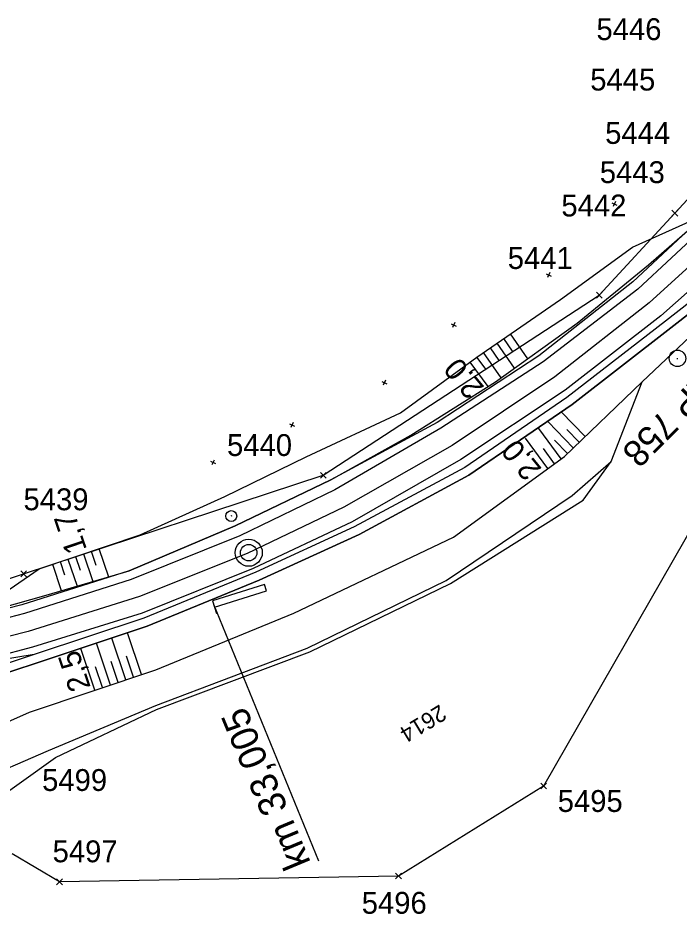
# Model space of a CAD drawing. Extents: x -804166 to -803706, y -1151030 to -1150147.
# Drawn here: x -803967.8 to -803907.3, y -1150746 to -1150663.9 of the extents above; entities that cross this region are included whole.
import ezdxf

# ---------------------------------------------------------------- set-up
doc = ezdxf.new("R2010")
doc.units = 0
for name, color, linetype in [('0381KM032-037P - Vrstva 1', 7, 'Continuous'), ('0381KM032-037P - Vrstva 13', 7, 'Continuous'), ('0381KM032-037P - Vrstva 4', 7, 'Continuous'), ('0381KM032-037P - Vrstva 48', 7, 'Continuous'), ('0381KM032-037P - Vrstva 49', 7, 'Continuous'), ('0381KM032-037P - Vrstva 57', 7, 'Continuous'), ('0381KM032-037P - Vrstva 7', 7, 'Continuous'), ('0381KM032-037P - Vrstva 9', 7, 'Continuous'), ('szdc - hran DP', 7, 'Continuous'), ('szdc - szdc_cislo', 7, 'Continuous'), ('szdc - szdc_krizek', 7, 'Continuous'), ('vyt_sit - stávající', 7, 'Continuous')]:
    doc.layers.add(name, color=color, linetype=linetype)

msp = doc.modelspace()

# ---------------------------------------------------------------- linework, layer by layer
at = {"layer": '0381KM032-037P - Vrstva 1'}
msp.add_lwpolyline([(-803901.906, -1150682.605), (-803910.014, -1150690), (-803918.643, -1150696.775), (-803928.041, -1150703.062), (-803937.946, -1150708.688), (-803946.795, -1150712.932), (-803956.655, -1150716.869), (-803966.853, -1150720.098), (-803973.694, -1150721.813), (-803983.505, -1150723.682), (-803993.918, -1150724.91), (-804004.459, -1150725.421), (-804014.948, -1150725.206), (-804025.475, -1150724.252), (-804035.41, -1150722.673), (-804044.081, -1150720.735), (-804054.774, -1150717.615), (-804061.472, -1150715.138)], dxfattribs=at)
at = {"layer": '0381KM032-037P - Vrstva 13'}
for points in [[(-803902.54, -1150686.99), (-803908.533, -1150691.682), (-803917.537, -1150698.646), (-803926.885, -1150705.063), (-803937.003, -1150710.487), (-803946.017, -1150714.661), (-803956.263, -1150718.85), (-803966.288, -1150722.189), (-803972.538, -1150724.259)], [(-803972.286, -1150725.012), (-803966.125, -1150722.974), (-803955.955, -1150719.581), (-803945.709, -1150715.376), (-803936.565, -1150711.19), (-803926.506, -1150705.78), (-803917.073, -1150699.315), (-803908.044, -1150692.29), (-803902.092, -1150687.65)]]:
    msp.add_lwpolyline(points, dxfattribs=at)
at = {"layer": '0381KM032-037P - Vrstva 4'}
msp.add_line((-803966.288, -1150722.189), (-803973.383, -1150723.337), dxfattribs=at)
for points in [[(-803904.886, -1150683.001), (-803906.516, -1150683.391), (-803911.518, -1150688.069), (-803920.109, -1150694.835), (-803929.412, -1150700.935), (-803939.155, -1150706.209), (-803947.889, -1150710.398), (-803957.601, -1150714.533), (-803967.413, -1150717.637)], [(-803904.886, -1150683.001), (-803911.05, -1150688.735), (-803919.705, -1150695.384), (-803929.087, -1150701.477), (-803938.787, -1150707.105), (-803947.481, -1150711.337), (-803957.418, -1150715.321), (-803967.176, -1150718.433)], [(-803902.503, -1150685.469), (-803908.943, -1150691.185), (-803917.694, -1150697.991), (-803927.241, -1150704.348), (-803937.195, -1150710.055), (-803946.246, -1150714.302), (-803956.405, -1150718.419), (-803966.448, -1150721.526)], [(-803902.503, -1150685.469), (-803902.54, -1150686.99), (-803908.533, -1150691.682), (-803917.537, -1150698.646), (-803926.885, -1150705.063), (-803937.003, -1150710.487), (-803946.017, -1150714.661), (-803956.263, -1150718.85), (-803966.288, -1150722.189)], [(-803967.413, -1150717.637), (-803975.823, -1150719.769), (-803983.88, -1150721.36), (-803994.176, -1150722.403), (-804004.636, -1150722.95), (-804014.864, -1150722.688), (-804025.142, -1150721.989), (-804034.984, -1150720.624), (-804043.408, -1150718.773), (-804051.925, -1150716.215), (-804054.245, -1150715.484), (-804061.999, -1150712.588)], [(-803967.176, -1150718.433), (-803974.218, -1150720.269), (-803983.735, -1150722.132), (-803994.129, -1150723.262), (-804004.519, -1150723.869), (-804015.047, -1150723.539), (-804025.265, -1150722.781), (-804035.168, -1150721.131), (-804043.667, -1150719.322), (-804054.385, -1150716.187), (-804061.833, -1150713.392)], [(-803966.448, -1150721.526), (-803973.383, -1150723.337), (-803975.353, -1150723.792), (-803983.323, -1150725.373), (-803993.816, -1150726.434), (-804004.802, -1150726.955), (-804015.292, -1150726.922), (-804025.602, -1150725.763), (-804035.878, -1150724.109), (-804044.498, -1150722.129), (-804055.401, -1150719.075), (-804061.092, -1150716.98)]]:
    msp.add_lwpolyline(points, dxfattribs=at)
at = {"layer": '0381KM032-037P - Vrstva 48'}
for p, q in [((-803923.341, -1150693.265), (-803922.553, -1150694.407)), ((-803922.724, -1150692.839), (-803921.156, -1150695.111)), ((-803924.575, -1150694.118), (-803923.779, -1150695.271)), ((-803923.958, -1150693.691), (-803922.374, -1150695.987)), ((-803925.193, -1150694.544), (-803923.592, -1150696.863)), ((-803926.415, -1150695.413), (-803924.777, -1150697.655)), ((-803925.809, -1150694.97), (-803924.975, -1150696.112)), ((-803915.883, -1150702.24), (-803918.059, -1150699.974)), ((-803918.079, -1150704.279), (-803920.11, -1150701.499)), ((-803916.965, -1150703.279), (-803919.272, -1150700.876)), ((-803916.424, -1150702.759), (-803917.545, -1150701.592)), ((-803919.291, -1150705.163), (-803921.33, -1150702.372)), ((-803917.506, -1150703.798), (-803918.692, -1150702.563)), ((-803918.685, -1150704.721), (-803919.698, -1150703.334)), ((-803961.787, -1150712.97), (-803960.933, -1150715.502)), ((-803961.077, -1150712.73), (-803960.645, -1150714.011)), ((-803960.366, -1150712.49), (-803959.492, -1150715.083)), ((-803963.919, -1150713.689), (-803963.508, -1150714.91)), ((-803963.209, -1150713.449), (-803962.375, -1150715.921)), ((-803962.498, -1150713.21), (-803962.076, -1150714.461)), ((-803964.63, -1150713.929), (-803963.816, -1150716.341)), ((-803956.479, -1150724.031), (-803957.763, -1150720.201)), ((-803959.324, -1150724.985), (-803960.603, -1150721.167)), ((-803957.902, -1150724.508), (-803959.183, -1150720.684)), ((-803960.746, -1150725.461), (-803962.023, -1150721.65)), ((-803958.613, -1150724.746), (-803959.253, -1150722.836)), ((-803957.19, -1150724.27), (-803957.832, -1150722.356)), ((-803960.035, -1150725.223), (-803960.674, -1150723.316))]:
    msp.add_line(p, q, dxfattribs=at)
at = {"layer": '0381KM032-037P - Vrstva 49'}
for p, q in [((-803913.423, -1150680.841), (-803912.971, -1150681.057)), ((-803913.089, -1150680.723), (-803913.305, -1150681.175)), ((-803919.449, -1150687.332), (-803918.997, -1150687.548)), ((-803919.115, -1150687.214), (-803919.331, -1150687.666)), ((-803928.133, -1150691.918), (-803927.681, -1150692.134)), ((-803927.799, -1150691.8), (-803928.015, -1150692.252)), ((-803934.479, -1150697.185), (-803934.027, -1150697.401)), ((-803934.145, -1150697.067), (-803934.361, -1150697.519)), ((-803942.927, -1150701.07), (-803942.475, -1150701.286)), ((-803942.593, -1150700.952), (-803942.809, -1150701.404)), ((-803950.166, -1150704.501), (-803949.714, -1150704.717)), ((-803949.832, -1150704.383), (-803950.048, -1150704.835))]:
    msp.add_line(p, q, dxfattribs=at)
for points in [[(-803984.817, -1150721.442), (-803974.636, -1150719.233), (-803973.09, -1150718.927), (-803972.805, -1150718.807), (-803972.246, -1150718.741), (-803965.21, -1150716.746), (-803957.601, -1150714.533), (-803947.889, -1150710.398), (-803939.155, -1150706.209), (-803931.831, -1150702.119), (-803924.086, -1150697.218), (-803916.608, -1150691.841), (-803910.081, -1150686.51), (-803906.516, -1150683.391), (-803903.605, -1150681.318)], [(-803972.246, -1150718.741), (-803965.841, -1150714.337), (-803956.596, -1150711.219), (-803948.841, -1150707.727), (-803941.393, -1150704.085), (-803932.776, -1150700.061), (-803925.787, -1150694.954), (-803918.146, -1150689.679), (-803911.549, -1150684.903), (-803903.605, -1150681.318)], [(-803973.24, -1150730.36), (-803966.718, -1150727.463), (-803955.163, -1150723.59), (-803942.536, -1150718.416), (-803927.909, -1150711.458), (-803917.773, -1150704.055), (-803910.649, -1150697.212), (-803903.52, -1150690.487), (-803900.099, -1150686.57)], [(-803902.092, -1150687.65), (-803908.044, -1150692.29), (-803917.073, -1150699.315), (-803926.506, -1150705.78), (-803936.565, -1150711.19), (-803945.709, -1150715.376), (-803955.955, -1150719.581), (-803966.125, -1150722.974), (-803972.286, -1150725.012), (-803974.7, -1150725.768), (-803983.368, -1150727.37), (-803993.836, -1150727.905), (-804004.989, -1150728.615), (-804004.868, -1150729.928), (-804012.985, -1150730.258), (-804018.762, -1150729.808), (-804029.792, -1150728.642), (-804054.152, -1150723.147), (-804060.274, -1150720.943)], [(-803970.39, -1150735.93), (-803964.347, -1150731.606), (-803955.102, -1150727.225), (-803941.078, -1150721.948), (-803928.207, -1150715.68), (-803916.068, -1150708.06), (-803913.504, -1150704.534), (-803910.649, -1150697.212)], [(-803971.76, -1150733.922), (-803964.987, -1150730.973), (-803955.152, -1150726.847), (-803941.304, -1150721.616), (-803928.584, -1150715.413), (-803917.051, -1150707.621), (-803913.504, -1150704.534)]]:
    msp.add_lwpolyline(points, dxfattribs=at)
at = {"layer": '0381KM032-037P - Vrstva 7'}
msp.add_line((-803948.213, -1150709.499), (-803948.305, -1150709.537), dxfattribs=at)
for centre, radius in [((-803948.259, -1150709.518), 0.5), ((-803946.663, -1150712.869), 1.246), ((-803946.663, -1150712.869), 0.752)]:
    msp.add_circle(centre, radius, dxfattribs=at)
at = {"layer": '0381KM032-037P - Vrstva 9'}
for p, q in [((-803945.217, -1150715.777), (-803949.983, -1150717.29)), ((-803945.036, -1150716.348), (-803945.217, -1150715.777)), ((-803949.801, -1150717.862), (-803945.036, -1150716.348)), ((-803949.983, -1150717.29), (-803949.801, -1150717.862)), ((-803949.892, -1150717.576), (-803940.281, -1150741.083)), ((-803949.801, -1150717.862), (-803949.62, -1150718.434))]:
    msp.add_line(p, q, dxfattribs=at)
at = {"layer": 'szdc - hran DP'}
for p, q in [((-803907.67, -1150681.78), (-803903.98, -1150677.77)), ((-803914.58, -1150689.29), (-803907.67, -1150681.78)), ((-803939.84, -1150705.78), (-803914.58, -1150689.29)), ((-803967.26, -1150714.81), (-803939.84, -1150705.78)), ((-803905.7, -1150709.82), (-803919.68, -1150734.23)), ((-803976.9, -1150717.98), (-803967.26, -1150714.81)), ((-803919.68, -1150734.23), (-803932.96, -1150742.47)), ((-803963.98, -1150743), (-803968.3, -1150740.45)), ((-803932.96, -1150742.47), (-803963.98, -1150743))]:
    msp.add_line(p, q, dxfattribs=at)
at = {"layer": 'szdc - szdc_krizek'}
for p, q in [((-803907.405, -1150682.045), (-803907.936, -1150681.515)), ((-803907.936, -1150682.045), (-803907.405, -1150681.515)), ((-803914.315, -1150689.555), (-803914.846, -1150689.025)), ((-803914.846, -1150689.555), (-803914.315, -1150689.025)), ((-803939.575, -1150706.045), (-803940.106, -1150705.515)), ((-803940.106, -1150706.045), (-803939.575, -1150705.515)), ((-803966.995, -1150715.075), (-803967.526, -1150714.545)), ((-803967.526, -1150715.075), (-803966.995, -1150714.545)), ((-803919.415, -1150734.495), (-803919.946, -1150733.965)), ((-803919.946, -1150734.495), (-803919.415, -1150733.965)), ((-803932.695, -1150742.735), (-803933.226, -1150742.205)), ((-803933.226, -1150742.735), (-803932.695, -1150742.205)), ((-803963.715, -1150743.265), (-803964.246, -1150742.735)), ((-803964.246, -1150743.265), (-803963.715, -1150742.735))]:
    msp.add_line(p, q, dxfattribs=at)
at = {"layer": 'vyt_sit - stávající'}
msp.add_line((-803907.48, -1150695.075), (-803907.38, -1150695.075), dxfattribs=at)
msp.add_circle((-803907.43, -1150695.075), 0.756, dxfattribs=at)

# ---------------------------------------------------------------- texts
at = {"layer": '0381KM032-037P - Vrstva 48'}
for s, rotation, p in [('2,0', 129.61944, (-803925.039, -1150697.72)), ('2,0', 129.42518, (-803919.779, -1150705.196)), ('1,7', 108.63737, (-803961.445, -1150712.571)), ('2,5', 108.45016, (-803961.097, -1150725.192))]:
    msp.add_text(s, height=2, rotation=rotation, dxfattribs=at).set_placement(p)
at = {"layer": '0381KM032-037P - Vrstva 57'}
msp.add_text('2614', height=1.5, rotation=211.19956, dxfattribs=at).set_placement((-803929.177, -1150726.725))
at = {"layer": '0381KM032-037P - Vrstva 9'}
msp.add_text('km 33,005', height=2.5, rotation=112.61933, dxfattribs=at).set_placement((-803940.96, -1150741.243))
at = {"layer": 'szdc - szdc_cislo'}
for s, p in [('5446', (-803914.842, -1150665.938)), ('5445', (-803915.41, -1150670.556)), ('5444', (-803914.043, -1150675.44)), ('5443', (-803914.536, -1150679.031)), ('5442', (-803918.052, -1150682.083)), ('5441', (-803922.96, -1150686.892)), ('5440', (-803948.647, -1150704.016)), ('5439', (-803967.272, -1150708.982)), ('5499', (-803965.569, -1150734.683)), ('5495', (-803918.385, -1150736.604)), ('5497', (-803964.609, -1150741.212)), ('5496', (-803936.321, -1150745.927))]:
    msp.add_text(s, height=2, dxfattribs=at).set_placement(p)
at = {"layer": 'vyt_sit - stávající'}
msp.add_text('ŽP 758', height=2.4, rotation=225, dxfattribs=at).set_placement((-803905.333, -1150696.219))

doc.saveas('drawing.dxf')
